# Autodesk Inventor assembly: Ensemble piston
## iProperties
Shininess: 41.0
Length Units: 11269
Angle Units: 11279
Time Units: 11290
Mass Units: 11283
Length Display Precision: 3
Angle Display Precision: 2
Created: 2002-11
Part Number: Ensemble piston
Document SubType Name: Assemblage
Designer: poste-2
Density: 0.0
Volumn: 0.0
Area: 0.0
PropertySet Name: Model Information
Control State: 0
Master: False
Checked Out: False
Author: poste-2
